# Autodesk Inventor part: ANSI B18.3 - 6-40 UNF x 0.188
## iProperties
IsCustomPart: 0
Created: 2008-02
Part Number: ANSI B18.3 - 6-40 UNF x 0.188
Material: Steel, Mild
Description: Hexagon Socket Set Screw - Flat Point
Document SubType Name: Modeling
Standard: ANSI B18.3
Standard Revision: 2003
Standards Organization: ANSI
Language: en-US
Size Designation: 6-40 UNF x 0.188
Categories: <MemberInstance><Categories><Category DisplayName="Fasteners" InternalName="e4da775c-781d-43d5-af7c-5136215cf5a6" Mnemonic="FSTN"><Category DisplayName="Bolts"
Density: 1 g/cm^3
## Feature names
1. Body [Revolution]
2. Chamfer1
3. Slot [Extrusion]
4. Chamfer2
